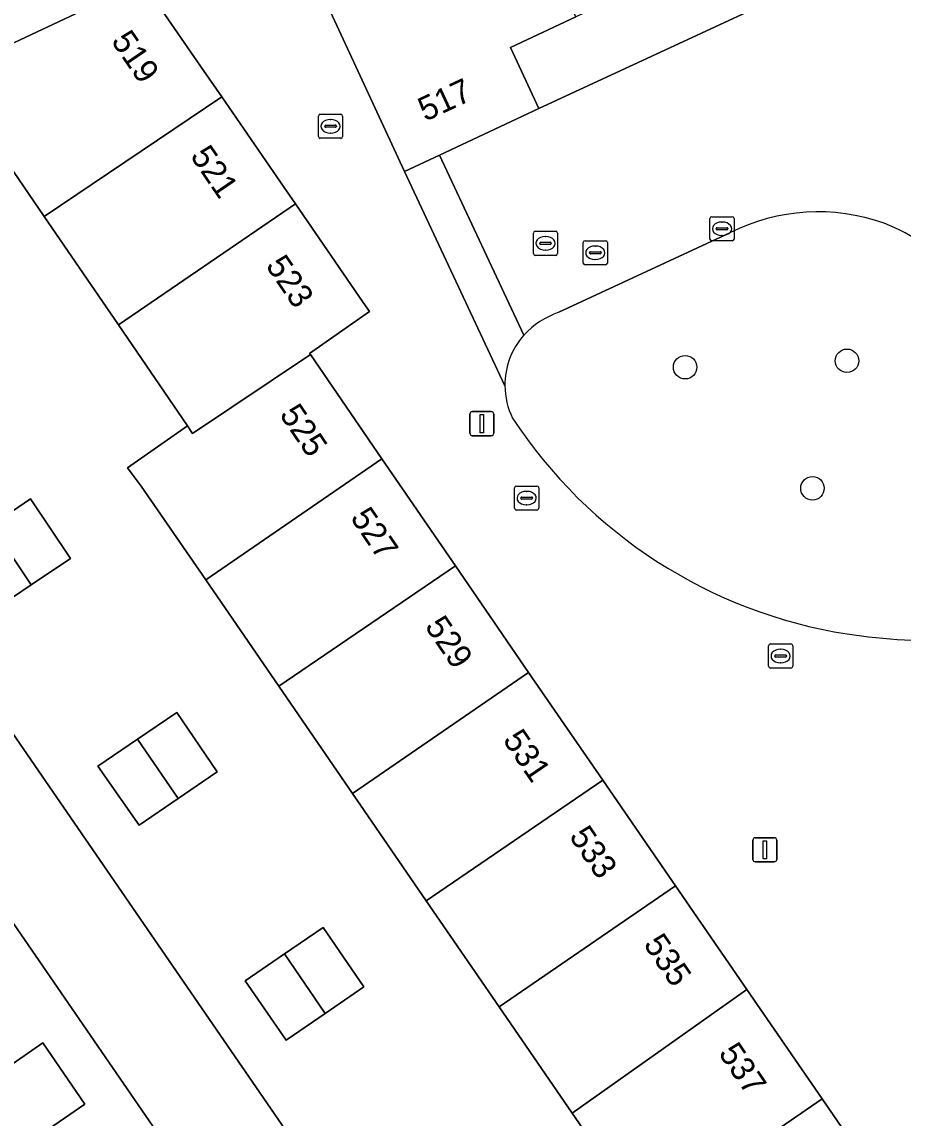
# Model space of a CAD drawing. Extents: x 155275 to 156265, y 382654 to 383635.
# Drawn here: x 155728.69 to 155765.33, y 383513.37 to 383558.94 of the extents above; entities that cross this region are included whole.
import ezdxf

# ---------------------------------------------------------------- set-up
doc = ezdxf.new("R2010")
doc.units = 0
for name, color, linetype in [('IMGEO_Boom', 7, 'Continuous'), ('IMGEO_Erf', 7, 'Continuous'), ('IMGEO_Groenvoorziening', 7, 'Continuous'), ('IMGEO_Kolk', 7, 'Continuous'), ('IMGEO_Lichtmast', 7, 'Continuous'), ('IMGEO_Pand', 7, 'Continuous'), ('IMGEO_Pand_nummerreeks', 7, 'Continuous'), ('IMGEO_Parkeervlak_open', 7, 'Continuous'), ('IMGEO_Rijbaan_lokaal_open', 7, 'Continuous'), ('IMGEO_Rioolput', 7, 'Continuous'), ('IMGEO_Voetpad_op_trap', 7, 'Continuous')]:
    doc.layers.add(name, color=color, linetype=linetype)

msp = doc.modelspace()

# ---------------------------------------------------------------- linework, layer by layer
at = {"layer": 'IMGEO_Boom'}
for centre in [(155756.268, 383544.588), (155763, 383544.855), (155761.563, 383539.555)]:
    msp.add_circle(centre, 0.489, dxfattribs=at)
at = {"layer": 'IMGEO_Erf'}
for points in [[(155761.083, 383560.403), (155759.879, 383562.955), (155757.162, 383561.687), (155754.448, 383560.42), (155751.727, 383559.15), (155749.004, 383557.879), (155750.18, 383555.34)], [(155729.07, 383535.535), (155727.429, 383534.434), (155725.723, 383536.875), (155727.41, 383538.008), (155729.051, 383539.109), (155730.71, 383536.636)], [(155735.185, 383526.656), (155733.558, 383525.546), (155731.845, 383528.002), (155733.498, 383529.129), (155735.125, 383530.238), (155736.812, 383527.765)], [(155741.293, 383517.718), (155739.677, 383516.615), (155737.967, 383519.078), (155739.603, 383520.194), (155741.219, 383521.296), (155742.909, 383518.82)]]:
    msp.add_lwpolyline(points, close=True, dxfattribs=at)
msp.add_lwpolyline([(155726.768, 383531.573), (155770.822, 383467.542), (155779.252, 383473.301), (155776.091, 383477.9), (155773.031, 383482.352), (155769.971, 383486.803), (155766.894, 383491.28), (155763.817, 383495.756), (155760.755, 383500.211), (155757.693, 383504.666), (155754.631, 383509.121), (155751.569, 383513.576), (155748.535, 383517.99), (155745.501, 383522.404), (155742.436, 383526.863), (155739.371, 383531.322), (155736.332, 383535.743), (155733.649, 383539.647), (155733.271, 383540.147), (155733.075, 383540.407), (155735.571, 383542.155), (155732.704, 383546.343), (155729.619, 383550.85), (155725.564, 383556.774)], dxfattribs=at)
at = {"layer": 'IMGEO_Groenvoorziening'}
for points in [[(155787.443, 383580.326), (155739.14, 383598.152), (155728.415, 383578.025), (155723.779, 383572.112), (155718.824, 383567.292), (155715.552, 383564.773), (155712.75, 383562.971), (155712.449, 383561.816), (155712.203, 383558.44), (155712.637, 383554.67), (155713.005, 383550.789), (155713.312, 383550.934), (155725.564, 383556.774), (155733.714, 383560.605), (155733.831, 383560.435), (155739.788, 383563.171), (155739.706, 383563.353), (155745.24, 383565.955), (155756.128, 383571.033), (155761.492, 383573.541), (155766.856, 383576.049), (155781.073, 383582.648), (155787.443, 383580.326)], [(155758.134, 383550.177), (155751.016, 383546.872)], [(155727.024, 383511.005), (155731.306, 383513.946), (155729.557, 383516.497), (155725.308, 383513.54)]]:
    msp.add_lwpolyline(points, dxfattribs=at)
for centre, radius, start, end in [((155761.807, 383542.856), 8.191, 70.4981, 116.6457), ((155761.247, 383542.388), 8.827, 18.6662, 68.0833), ((155752.18, 383543.505), 3.562, 109.0631, 137.406), ((155751.891, 383543.847), 3.119, 138.44, 180.5138), ((155751.883, 383543.846), 3.111, 180.4888, 206.2196), ((155766.17, 383553.682), 20.429, 213.2837, 261.0815), ((155766.379, 383554.749), 21.516, 260.9724, 273.7682)]:
    msp.add_arc(centre, radius, start, end, dxfattribs=at)
at = {"layer": 'IMGEO_Kolk'}
for p, q in [((155741.022, 383554.178), (155741.022, 383555.03)), ((155741.097, 383555.104), (155741.949, 383555.104)), ((155742.023, 383555.03), (155742.023, 383554.178)), ((155741.281, 383554.598), (155741.281, 383554.61)), ((155741.719, 383554.561), (155741.321, 383554.561)), ((155741.324, 383554.647), (155741.722, 383554.647)), ((155741.51, 383554.884), (155741.535, 383554.884)), ((155741.765, 383554.61), (155741.765, 383554.598)), ((155741.949, 383554.104), (155741.097, 383554.104)), ((155741.533, 383554.324), (155741.508, 383554.324)), ((155757.302, 383549.917), (155757.302, 383550.769)), ((155757.377, 383550.843), (155758.229, 383550.843)), ((155757.79, 383550.623), (155757.815, 383550.623)), ((155758.303, 383550.769), (155758.303, 383549.917)), ((155757.561, 383550.337), (155757.561, 383550.349)), ((155757.999, 383550.3), (155757.601, 383550.3)), ((155757.604, 383550.386), (155758.002, 383550.386)), ((155757.813, 383550.063), (155757.788, 383550.063)), ((155758.045, 383550.349), (155758.045, 383550.337)), ((155758.229, 383549.843), (155757.377, 383549.843)), ((155749.178, 383538.721), (155749.178, 383539.573)), ((155749.253, 383539.647), (155750.105, 383539.647)), ((155750.179, 383539.573), (155750.179, 383538.721)), ((155749.437, 383539.141), (155749.437, 383539.153)), ((155749.875, 383539.104), (155749.477, 383539.104)), ((155749.48, 383539.19), (155749.878, 383539.19)), ((155749.666, 383539.427), (155749.691, 383539.427)), ((155749.921, 383539.153), (155749.921, 383539.141)), ((155750.105, 383538.647), (155749.253, 383538.647)), ((155749.689, 383538.867), (155749.664, 383538.867)), ((155759.74, 383532.154), (155759.74, 383533.006)), ((155759.815, 383533.08), (155760.667, 383533.08)), ((155760.228, 383532.86), (155760.253, 383532.86)), ((155760.741, 383533.006), (155760.741, 383532.154)), ((155759.999, 383532.574), (155759.999, 383532.586)), ((155760.437, 383532.537), (155760.039, 383532.537)), ((155760.042, 383532.623), (155760.44, 383532.623)), ((155760.251, 383532.3), (155760.226, 383532.3)), ((155760.483, 383532.586), (155760.483, 383532.574)), ((155760.667, 383532.08), (155759.815, 383532.08))]:
    msp.add_line(p, q, dxfattribs=at)
for points in [[(155741.022, 383554.178), (155741.022, 383555.03)], [(155741.097, 383555.104), (155741.949, 383555.104)], [(155742.023, 383555.03), (155742.023, 383554.178)], [(155741.949, 383554.104), (155741.097, 383554.104)], [(155757.302, 383549.917), (155757.302, 383550.769)], [(155757.377, 383550.843), (155758.229, 383550.843)], [(155758.303, 383550.769), (155758.303, 383549.917)], [(155758.229, 383549.843), (155757.377, 383549.843)], [(155749.178, 383538.721), (155749.178, 383539.573)], [(155749.253, 383539.647), (155750.105, 383539.647)], [(155750.179, 383539.573), (155750.179, 383538.721)], [(155750.105, 383538.647), (155749.253, 383538.647)], [(155759.74, 383532.154), (155759.74, 383533.006)], [(155759.815, 383533.08), (155760.667, 383533.08)], [(155760.741, 383533.006), (155760.741, 383532.154)], [(155760.667, 383532.08), (155759.815, 383532.08)]]:
    msp.add_lwpolyline(points, dxfattribs=at)
for centre, radius, start, end in [((155741.099, 383555.028), 0.0765, 91.552, 178.448), ((155741.099, 383555.028), 0.0765, 91.552, 178.448), ((155741.947, 383555.028), 0.0765, 1.552, 88.448), ((155741.947, 383555.028), 0.0765, 1.552, 88.448), ((155741.321, 383554.607), 0.0403, 85.8775, 175.7526), ((155741.318, 383554.597), 0.0366, 178.938, 274.7102), ((155741.722, 383554.604), 0.043, 264.8664, 352.4533), ((155741.726, 383554.609), 0.0386, 1.7309, 96.639), ((155741.099, 383554.18), 0.0765, 181.552, 268.448), ((155741.099, 383554.18), 0.0765, 181.552, 268.448), ((155741.947, 383554.18), 0.0765, 271.552, 358.448), ((155741.947, 383554.18), 0.0765, 271.552, 358.448), ((155757.379, 383550.767), 0.0765, 91.552, 178.448), ((155757.379, 383550.767), 0.0765, 91.552, 178.448), ((155758.227, 383550.767), 0.0765, 1.552, 88.448), ((155758.227, 383550.767), 0.0765, 1.552, 88.448), ((155757.601, 383550.346), 0.0403, 85.8775, 175.7526), ((155757.598, 383550.336), 0.0366, 178.938, 274.7102), ((155758.002, 383550.343), 0.043, 264.8664, 352.4533), ((155758.006, 383550.348), 0.0386, 1.7309, 96.639), ((155757.379, 383549.919), 0.0765, 181.552, 268.448), ((155757.379, 383549.919), 0.0765, 181.552, 268.448), ((155758.227, 383549.919), 0.0765, 271.552, 358.448), ((155758.227, 383549.919), 0.0765, 271.552, 358.448), ((155749.255, 383539.571), 0.0765, 91.552, 178.448), ((155749.255, 383539.571), 0.0765, 91.552, 178.448), ((155750.103, 383539.571), 0.0765, 1.552, 88.448), ((155750.103, 383539.571), 0.0765, 1.552, 88.448), ((155749.477, 383539.15), 0.0403, 85.8775, 175.7526), ((155749.474, 383539.14), 0.0366, 178.938, 274.7102), ((155749.878, 383539.147), 0.043, 264.8664, 352.4533), ((155749.882, 383539.152), 0.0386, 1.7309, 96.639), ((155749.255, 383538.723), 0.0765, 181.552, 268.448), ((155749.255, 383538.723), 0.0765, 181.552, 268.448), ((155750.103, 383538.723), 0.0765, 271.552, 358.448), ((155750.103, 383538.723), 0.0765, 271.552, 358.448), ((155759.817, 383533.004), 0.0765, 91.552, 178.448), ((155759.817, 383533.004), 0.0765, 91.552, 178.448), ((155760.665, 383533.004), 0.0765, 1.552, 88.448), ((155760.665, 383533.004), 0.0765, 1.552, 88.448), ((155760.039, 383532.583), 0.0403, 85.8775, 175.7526), ((155760.036, 383532.573), 0.0366, 178.938, 274.7102), ((155760.44, 383532.58), 0.043, 264.8664, 352.4533), ((155760.444, 383532.585), 0.0386, 1.7309, 96.639), ((155759.817, 383532.156), 0.0765, 181.552, 268.448), ((155759.817, 383532.156), 0.0765, 181.552, 268.448), ((155760.665, 383532.156), 0.0765, 271.552, 358.448), ((155760.665, 383532.156), 0.0765, 271.552, 358.448)]:
    msp.add_arc(centre, radius, start, end, dxfattribs=at)
for centre, major_axis, ratio, start_param, end_param in [((155741.509, 383554.604), (-0.387, 0.002), 0.722429, 4.712389, 7.853982), ((155741.534, 383554.604), (-0.39, 0.002), 0.717154, 1.570796, 4.712389), ((155757.789, 383550.343), (-0.387, 0.002), 0.722429, 4.712389, 7.853982), ((155757.814, 383550.343), (-0.39, 0.002), 0.717154, 1.570796, 4.712389), ((155749.665, 383539.147), (-0.387, 0.002), 0.722429, 4.712389, 7.853982), ((155749.69, 383539.147), (-0.39, 0.002), 0.717154, 1.570796, 4.712389), ((155760.227, 383532.58), (-0.387, 0.002), 0.722429, 4.712389, 7.853982), ((155760.252, 383532.58), (-0.39, 0.002), 0.717154, 1.570796, 4.712389)]:
    msp.add_ellipse(centre, major_axis=major_axis, ratio=ratio, start_param=start_param, end_param=end_param, dxfattribs=at)
at = {"layer": 'IMGEO_Lichtmast'}
for p, q in [((155747.419, 383542.741), (155748.209, 383542.741)), ((155748.209, 383542.741), (155747.419, 383542.741)), ((155747.319, 383541.841), (155747.319, 383542.641)), ((155747.319, 383542.641), (155747.319, 383541.841)), ((155748.309, 383542.641), (155748.309, 383541.841)), ((155748.309, 383541.841), (155748.309, 383542.641)), ((155748.209, 383541.741), (155747.419, 383541.741)), ((155747.419, 383541.741), (155748.209, 383541.741)), ((155759.088, 383524.124), (155759.088, 383524.924)), ((155759.088, 383524.924), (155759.088, 383524.124)), ((155759.188, 383525.024), (155759.978, 383525.024)), ((155759.978, 383525.024), (155759.188, 383525.024)), ((155760.078, 383524.924), (155760.078, 383524.124)), ((155760.078, 383524.124), (155760.078, 383524.924)), ((155759.978, 383524.024), (155759.188, 383524.024)), ((155759.188, 383524.024), (155759.978, 383524.024))]:
    msp.add_line(p, q, dxfattribs=at)
for points in [[(155747.739, 383542.616), (155747.889, 383542.616), (155747.889, 383541.866), (155747.739, 383541.866), (155747.739, 383542.616)], [(155759.508, 383524.899), (155759.658, 383524.899), (155759.658, 383524.149), (155759.508, 383524.149), (155759.508, 383524.899)]]:
    msp.add_lwpolyline(points, dxfattribs=at)
for centre, start, end in [((155747.419, 383542.641), 90, 180), ((155747.419, 383542.641), 90, 180), ((155748.209, 383542.641), 0, 90), ((155748.209, 383542.641), 360, 90), ((155747.419, 383541.841), 180, 270), ((155747.419, 383541.841), 180, 270), ((155748.209, 383541.841), 270, 0), ((155748.209, 383541.841), 270, 0), ((155759.188, 383524.924), 90, 180), ((155759.188, 383524.924), 90, 180), ((155759.978, 383524.924), 0, 90), ((155759.978, 383524.924), 360, 90), ((155759.188, 383524.124), 180, 270), ((155759.188, 383524.124), 180, 270), ((155759.978, 383524.124), 270, 0), ((155759.978, 383524.124), 270, 0)]:
    msp.add_arc(centre, 0.1, start, end, dxfattribs=at)
at = {"layer": 'IMGEO_Pand'}
for points in [[(155745.24, 383565.955), (155739.706, 383563.353), (155739.788, 383563.171), (155740.815, 383560.903), (155744.597, 383552.72), (155746.058, 383553.406), (155750.18, 383555.34), (155749.004, 383557.879), (155751.727, 383559.15), (155750.654, 383561.465), (155747.937, 383560.205)], [(155736.243, 383556.928), (155733.831, 383560.435), (155733.714, 383560.605), (155725.564, 383556.774), (155729.619, 383550.85), (155736.997, 383555.832)], [(155740.06, 383551.379), (155739.59, 383552.062), (155736.997, 383555.832), (155729.619, 383550.85), (155732.704, 383546.343)], [(155740.684, 383545.12), (155740.654, 383545.164), (155743.137, 383546.906), (155742.883, 383547.276), (155740.06, 383551.379), (155732.704, 383546.343), (155735.571, 383542.155), (155735.789, 383541.836)], [(155743.662, 383540.781), (155740.684, 383545.12), (155735.789, 383541.836), (155735.571, 383542.155), (155733.075, 383540.407), (155733.271, 383540.147), (155733.649, 383539.647), (155736.332, 383535.743)], [(155746.715, 383536.332), (155743.662, 383540.781), (155736.332, 383535.743), (155739.371, 383531.322)], [(155729.051, 383539.109), (155727.41, 383538.008), (155729.07, 383535.535), (155730.71, 383536.636)], [(155727.41, 383538.008), (155725.723, 383536.875), (155727.429, 383534.434), (155729.07, 383535.535)], [(155749.758, 383531.896), (155746.715, 383536.332), (155739.371, 383531.322), (155742.436, 383526.863)], [(155752.842, 383527.415), (155749.758, 383531.896), (155742.436, 383526.863), (155745.501, 383522.404)], [(155735.125, 383530.238), (155733.498, 383529.129), (155735.185, 383526.656), (155736.812, 383527.765)], [(155733.498, 383529.129), (155731.845, 383528.002), (155733.558, 383525.546), (155735.185, 383526.656)], [(155755.863, 383523.027), (155752.842, 383527.415), (155745.501, 383522.404), (155748.535, 383517.99)], [(155758.836, 383518.709), (155755.863, 383523.027), (155748.535, 383517.99), (155751.569, 383513.576)], [(155741.219, 383521.296), (155739.603, 383520.194), (155741.293, 383517.718), (155742.909, 383518.82)], [(155739.603, 383520.194), (155737.967, 383519.078), (155739.677, 383516.615), (155741.293, 383517.718)], [(155761.966, 383514.163), (155758.836, 383518.709), (155751.569, 383513.576), (155754.631, 383509.121)], [(155765.007, 383509.747), (155761.966, 383514.163), (155754.631, 383509.121), (155757.693, 383504.666)]]:
    msp.add_lwpolyline(points, close=True, dxfattribs=at)
at = {"layer": 'IMGEO_Parkeervlak_open'}
msp.add_lwpolyline([(155725.308, 383513.54), (155729.557, 383516.497), (155731.306, 383513.946), (155727.024, 383511.005), (155732.916, 383502.493), (155737.163, 383505.396), (155738.404, 383503.602), (155734.166, 383500.672), (155735.683, 383498.451), (155739.9, 383501.331), (155741.447, 383502.388), (155712.314, 383544.743)], dxfattribs=at)
at = {"layer": 'IMGEO_Rijbaan_lokaal_open'}
for points in [[(155785.087, 383568.733), (155781.636, 383569.994), (155771.84, 383565.423), (155766.461, 383562.913), (155761.083, 383560.403), (155750.18, 383555.34), (155746.058, 383553.406), (155749.557, 383545.916)], [(155748.772, 383543.819), (155744.597, 383552.72), (155740.815, 383560.903), (155739.788, 383563.171), (155733.831, 383560.435), (155736.243, 383556.928), (155736.997, 383555.832), (155739.59, 383552.062), (155740.06, 383551.379), (155742.883, 383547.276), (155743.137, 383546.906), (155740.654, 383545.164), (155740.684, 383545.12), (155743.662, 383540.781), (155746.715, 383536.332), (155749.758, 383531.896), (155752.842, 383527.415), (155755.863, 383523.027), (155758.836, 383518.709), (155761.966, 383514.163), (155765.007, 383509.747)], [(155775.496, 383460.748), (155770.822, 383467.542), (155726.768, 383531.573), (155713.312, 383550.934), (155713.005, 383550.789), (155711.998, 383550.314), (155709.381, 383549.08), (155709.684, 383548.566), (155712.314, 383544.743), (155741.447, 383502.388), (155743.722, 383499.066), (155744.391, 383498.089), (155746.332, 383495.256), (155782.062, 383443.394), (155782.858, 383445.59), (155787.734, 383459.039), (155789.443, 383463.684), (155790.398, 383466.305), (155793.345, 383474.395), (155794.304, 383477.026)], [(155751.016, 383546.872), (155758.134, 383550.177)]]:
    msp.add_lwpolyline(points, dxfattribs=at)
for centre, radius, start, end in [((155761.807, 383542.856), 8.191, 70.4981, 116.6457), ((155761.247, 383542.388), 8.827, 18.6662, 68.0833), ((155752.18, 383543.505), 3.562, 109.0631, 137.406), ((155751.883, 383543.846), 3.111, 180.4888, 206.2196), ((155766.17, 383553.682), 20.429, 213.2837, 261.0815), ((155766.379, 383554.749), 21.516, 260.9724, 273.7682)]:
    msp.add_arc(centre, radius, start, end, dxfattribs=at)
at = {"layer": 'IMGEO_Rioolput'}
for p, q in [((155749.961, 383549.313), (155749.961, 383550.165)), ((155750.036, 383550.239), (155750.888, 383550.239)), ((155750.449, 383550.019), (155750.474, 383550.019)), ((155750.962, 383550.165), (155750.962, 383549.313)), ((155750.22, 383549.733), (155750.22, 383549.745)), ((155750.658, 383549.696), (155750.26, 383549.696)), ((155750.263, 383549.782), (155750.661, 383549.782)), ((155750.704, 383549.745), (155750.704, 383549.733)), ((155752.033, 383548.919), (155752.033, 383549.771)), ((155752.108, 383549.845), (155752.96, 383549.845)), ((155752.521, 383549.625), (155752.546, 383549.625)), ((155753.034, 383549.771), (155753.034, 383548.919)), ((155750.888, 383549.239), (155750.036, 383549.239)), ((155750.472, 383549.459), (155750.447, 383549.459)), ((155752.292, 383549.339), (155752.292, 383549.351)), ((155752.73, 383549.302), (155752.332, 383549.302)), ((155752.335, 383549.388), (155752.733, 383549.388)), ((155752.544, 383549.065), (155752.519, 383549.065)), ((155752.776, 383549.351), (155752.776, 383549.339)), ((155752.96, 383548.845), (155752.108, 383548.845))]:
    msp.add_line(p, q, dxfattribs=at)
for points in [[(155749.961, 383549.313), (155749.961, 383550.165)], [(155750.036, 383550.239), (155750.888, 383550.239)], [(155750.962, 383550.165), (155750.962, 383549.313)], [(155752.033, 383548.919), (155752.033, 383549.771)], [(155752.108, 383549.845), (155752.96, 383549.845)], [(155753.034, 383549.771), (155753.034, 383548.919)], [(155750.888, 383549.239), (155750.036, 383549.239)], [(155752.96, 383548.845), (155752.108, 383548.845)]]:
    msp.add_lwpolyline(points, dxfattribs=at)
for centre, radius, start, end in [((155750.038, 383550.163), 0.0765, 91.552, 178.448), ((155750.038, 383550.163), 0.0765, 91.552, 178.448), ((155750.886, 383550.163), 0.0765, 1.552, 88.448), ((155750.886, 383550.163), 0.0765, 1.552, 88.448), ((155750.26, 383549.742), 0.0403, 85.8775, 175.7526), ((155750.257, 383549.732), 0.0366, 178.938, 274.7102), ((155750.661, 383549.739), 0.043, 264.8664, 352.4533), ((155750.665, 383549.744), 0.0386, 1.7309, 96.639), ((155752.11, 383549.769), 0.0765, 91.552, 178.448), ((155752.11, 383549.769), 0.0765, 91.552, 178.448), ((155752.958, 383549.769), 0.0765, 1.552, 88.448), ((155752.958, 383549.769), 0.0765, 1.552, 88.448), ((155750.038, 383549.315), 0.0765, 181.552, 268.448), ((155750.038, 383549.315), 0.0765, 181.552, 268.448), ((155750.886, 383549.315), 0.0765, 271.552, 358.448), ((155750.886, 383549.315), 0.0765, 271.552, 358.448), ((155752.332, 383549.348), 0.0403, 85.8775, 175.7526), ((155752.329, 383549.338), 0.0366, 178.938, 274.7102), ((155752.733, 383549.345), 0.043, 264.8664, 352.4533), ((155752.737, 383549.35), 0.0386, 1.7309, 96.639), ((155752.11, 383548.921), 0.0765, 181.552, 268.448), ((155752.11, 383548.921), 0.0765, 181.552, 268.448), ((155752.958, 383548.921), 0.0765, 271.552, 358.448), ((155752.958, 383548.921), 0.0765, 271.552, 358.448)]:
    msp.add_arc(centre, radius, start, end, dxfattribs=at)
for centre, major_axis, ratio, start_param, end_param in [((155750.448, 383549.739), (-0.387, 0.002), 0.722429, 4.712389, 7.853982), ((155750.473, 383549.739), (-0.39, 0.002), 0.717154, 1.570796, 4.712389), ((155752.52, 383549.345), (-0.387, 0.002), 0.722429, 4.712389, 7.853982), ((155752.545, 383549.345), (-0.39, 0.002), 0.717154, 1.570796, 4.712389)]:
    msp.add_ellipse(centre, major_axis=major_axis, ratio=ratio, start_param=start_param, end_param=end_param, dxfattribs=at)
at = {"layer": 'IMGEO_Voetpad_op_trap'}
for points in [[(155746.058, 383553.406), (155744.597, 383552.72), (155748.772, 383543.819)], [(155749.557, 383545.916), (155746.058, 383553.406)]]:
    msp.add_lwpolyline(points, dxfattribs=at)
msp.add_arc((155751.891, 383543.847), 3.119, 138.44, 180.5138, dxfattribs=at)

# ---------------------------------------------------------------- texts
at = {"layer": 'IMGEO_Pand_nummerreeks'}
for s, rotation, p in [('519', 304.32, (155732.374, 383558.149)), ('517', 24.9409, (155745.463, 383554.788)), ('521', 304.3257, (155735.663, 383553.368)), ('523', 304.3314, (155738.799, 383548.809)), ('525', 304.2627, (155739.374, 383542.618)), ('527', 304.2627, (155742.32, 383538.326)), ('529', 304.2512, (155745.418, 383533.811)), ('531', 304.3372, (155748.659, 383529.091)), ('533', 304.3486, (155751.42, 383525.08)), ('535', 304.3486, (155754.509, 383520.593)), ('537', 304.3543, (155757.628, 383516.065))]:
    msp.add_text(s, height=1, rotation=rotation, dxfattribs=at).set_placement(p)

doc.saveas('drawing.dxf')
